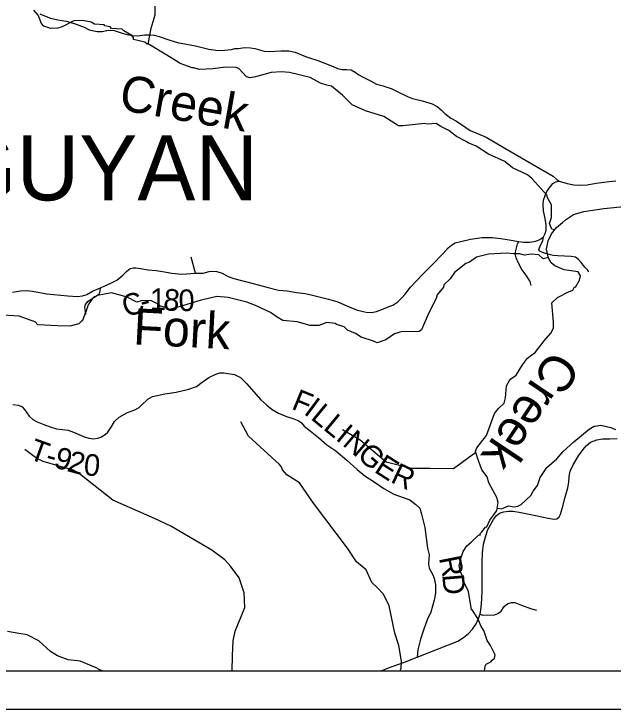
# Model space of a CAD drawing. Extents: x -1.8 to 75.7, y -2 to 25.
# Drawn here: x 45.012 to 46.582, y 15.612 to 17.434 of the extents above; entities that cross this region are included whole.
import ezdxf

# ---------------------------------------------------------------- set-up
doc = ezdxf.new("R2010")
doc.units = 0
for name, color, linetype in [('GM_X_County_Road', 7, 'Continuous'), ('GM_X_County_Road_Text', 7, 'Continuous'), ('GM_X_Minor_River', 7, 'Continuous'), ('GM_X_Minor_River_Text', 7, 'Continuous'), ('GM_X_State_Route', 7, 'Continuous'), ('GM_X_Township', 7, 'Continuous'), ('GM_X_Township_Road', 7, 'Continuous'), ('GM_X_Township_Road_Text', 7, 'Continuous'), ('GM_X_Township_ROW', 7, 'Continuous'), ('GM_X_Township_Text', 7, 'Continuous'), ('SH_Data', 7, 'Continuous')]:
    doc.layers.add(name, color=color, linetype=linetype)

msp = doc.modelspace()

# ---------------------------------------------------------------- linework, layer by layer
at = {"layer": 'GM_X_County_Road'}
for points in [[(45.08, 17.4349), (45.0918, 17.4291), (45.108, 17.423), (45.1272, 17.419), (45.1501, 17.4154), (45.1749, 17.4076), (45.196, 17.3993), (45.209, 17.3928), (45.2305, 17.3881), (45.2428, 17.3881), (45.2553, 17.391), (45.2654, 17.3917), (45.2744, 17.3908), (45.2957, 17.3841), (45.3087, 17.3805), (45.323, 17.3778), (45.3355, 17.3767), (45.3537, 17.3791), (45.3676, 17.3798), (45.3794, 17.3787), (45.3924, 17.3751), (45.4155, 17.3673), (45.4344, 17.3614), (45.4443, 17.3589)], [(45.4443, 17.3589), (45.4502, 17.3574), (45.4878, 17.3507), (45.523, 17.3424), (45.5414, 17.3391), (45.5555, 17.3382), (45.5819, 17.3415), (45.591, 17.3433), (45.5998, 17.3441), (45.6171, 17.3462), (45.6323, 17.3451), (45.6437, 17.3433), (45.6681, 17.337), (45.6827, 17.3355), (45.7114, 17.3379), (45.7324, 17.3377), (45.7492, 17.3341), (45.7759, 17.3229), (45.7865, 17.3193)], [(45.7865, 17.3193), (45.8081, 17.312), (45.8287, 17.3048), (45.8484, 17.2963), (45.8599, 17.2916), (45.8717, 17.2887), (45.8847, 17.2889), (45.8957, 17.2882), (45.9065, 17.2817), (45.9158, 17.2748), (45.9275, 17.2685), (45.9479, 17.258), (45.9619, 17.2503), (45.9797, 17.2456)], [(45.9797, 17.2456), (45.9837, 17.2445), (46.0008, 17.2389), (46.0182, 17.2304), (46.0417, 17.2185), (46.0436, 17.2178)], [(46.0436, 17.2178), (46.0568, 17.2125), (46.0814, 17.2062), (46.1076, 17.1986), (46.1213, 17.1919), (46.1316, 17.1832), (46.1416, 17.1729), (46.1573, 17.161), (46.1719, 17.1529), (46.1961, 17.1368), (46.2079, 17.129), (46.233, 17.1184), (46.2492, 17.1117), (46.2982, 17.0826), (46.369, 17.0414), (46.425, 17.0091), (46.435, 17.0001), (46.4411, 16.9957)], [(45.0082, 16.7053), (45.0296, 16.7086), (45.0449, 16.709), (45.0605, 16.7072), (45.0984, 16.7009), (45.1531, 16.6953), (45.1789, 16.6935), (45.1914, 16.6951), (45.2029, 16.699), (45.2177, 16.7072), (45.2384, 16.7167), (45.2501, 16.7216), (45.2643, 16.7281), (45.2812, 16.7367), (45.2973, 16.7494), (45.3066, 16.7588), (45.3119, 16.7632), (45.3168, 16.767), (45.324, 16.7688), (45.3317, 16.769), (45.344, 16.767), (45.3638, 16.7632), (45.3845, 16.7614), (45.4015, 16.759), (45.4261, 16.7546), (45.4522, 16.7525), (45.4875, 16.7551), (45.508, 16.7551), (45.5236, 16.7588), (45.5336, 16.76), (45.5434, 16.759), (45.5573, 16.7546), (45.5731, 16.7463), (45.5885, 16.7409), (45.6385, 16.7274), (45.678, 16.7169), (45.7055, 16.7104), (45.7278, 16.7081), (45.7522, 16.7041), (45.7755, 16.7011), (45.7941, 16.6972), (45.8364, 16.6867), (45.8604, 16.6797), (45.8862, 16.6686), (45.9097, 16.6588), (45.9276, 16.6539), (45.9353, 16.6526), (45.9488, 16.6521), (45.9625, 16.6541), (45.9804, 16.6614), (45.9911, 16.6658), (46.0048, 16.6711), (46.0183, 16.6797), (46.0286, 16.69), (46.0369, 16.7), (46.0516, 16.7179), (46.0825, 16.7514), (46.1081, 16.777), (46.1367, 16.8065), (46.1502, 16.8212), (46.1583, 16.8284), (46.1684, 16.8342), (46.1828, 16.8381), (46.2084, 16.8439), (46.2393, 16.8484), (46.2649, 16.8481), (46.2881, 16.8458), (46.31, 16.8419), (46.3349, 16.8379), (46.347, 16.8363), (46.3642, 16.8358), (46.3798, 16.8384), (46.3898, 16.843), (46.4, 16.8502), (46.4041, 16.8591), (46.4066, 16.8671), (46.4066, 16.8819), (46.4041, 16.8985), (46.3999, 16.9184), (46.3985, 16.9352), (46.4001, 16.946), (46.4039, 16.9587), (46.4097, 16.9708), (46.4178, 16.982), (46.4245, 16.9896), (46.4321, 16.9939), (46.4411, 16.9957)], [(46.4411, 16.9957), (46.4614, 16.9898), (46.4789, 16.9865), (46.4962, 16.9854), (46.5145, 16.9865), (46.5381, 16.9905), (46.5718, 16.9953), (46.589, 16.9966)]]:
    msp.add_lwpolyline(points, dxfattribs=at)
at = {"layer": 'GM_X_Minor_River'}
for points in [[(45.3634, 17.3541), (45.3715, 17.3971), (45.382, 17.4317), (45.382, 17.4571), (45.371, 17.5429), (45.3616, 17.5812), (45.3409, 17.6483), (45.323, 17.6933), (45.2876, 17.7726), (45.2847, 17.7773)], [(46.4287, 16.868), (46.4214, 16.8704), (46.4154, 16.8852), (46.421, 16.9005), (46.421, 16.9092), (46.4203, 16.9335), (46.4093, 16.9536), (46.4093, 16.9586), (46.3703, 17.0022), (46.3582, 17.0128), (46.3181, 17.0313), (46.2984, 17.0472), (46.2557, 17.0665), (46.2232, 17.0874), (46.202, 17.0968), (46.1986, 17.0991), (46.1717, 17.1127), (46.1513, 17.129), (46.1309, 17.1392), (46.1188, 17.1468), (46.0961, 17.1456), (46.0878, 17.1471), (46.0311, 17.1409), (46.0194, 17.1408), (45.9812, 17.1651), (45.9331, 17.1801), (45.898, 17.1964), (45.8734, 17.2218), (45.8446, 17.2449), (45.8352, 17.2468), (45.8318, 17.2479), (45.8151, 17.2528), (45.7883, 17.2676), (45.7342, 17.2811), (45.713, 17.2826), (45.6862, 17.2806), (45.6454, 17.2695), (45.631, 17.2664), (45.6216, 17.2698), (45.6015, 17.2911), (45.5943, 17.2941), (45.5675, 17.2951), (45.5331, 17.2901), (45.4979, 17.2885), (45.4828, 17.2934), (45.479, 17.2934), (45.4473, 17.3047), (45.4284, 17.3168), (45.3796, 17.3467), (45.3618, 17.357), (45.3607, 17.355), (45.3554, 17.3607), (45.3399, 17.3634), (45.3251, 17.3675), (45.3255, 17.3721), (45.3213, 17.3777), (45.3001, 17.3902), (45.2956, 17.3948), (45.268, 17.3959), (45.2642, 17.4004), (45.2502, 17.4034), (45.2483, 17.4057), (45.223, 17.4071), (45.2143, 17.4128), (45.192, 17.4169), (45.1689, 17.4165), (45.138, 17.4008), (45.1266, 17.397), (45.1085, 17.3962), (45.0903, 17.4022), (45.0843, 17.4094), (45.0756, 17.4315), (45.0638, 17.4443)], [(46.3449, 16.5143), (46.3582, 16.5317), (46.3692, 16.5408), (46.3783, 16.5465), (46.4013, 16.5774), (46.4187, 16.5972), (46.4258, 16.6109), (46.4258, 16.6265), (46.4212, 16.6766), (46.436, 16.6911), (46.4666, 16.7064), (46.4707, 16.7075), (46.4764, 16.7106), (46.4809, 16.7189), (46.484, 16.7178), (46.4938, 16.7368), (46.4964, 16.7482), (46.4907, 16.7585), (46.4537, 16.7633), (46.4291, 16.7743), (46.4196, 16.7823), (46.4132, 16.7944), (46.4075, 16.8176), (46.4116, 16.8392), (46.4211, 16.8583), (46.4335, 16.8743), (46.4498, 16.888), (46.457, 16.8945), (46.4785, 16.9082), (46.5053, 16.9166), (46.5575, 16.9243), (46.618, 16.9306)], [(46.4128, 16.7961), (46.3992, 16.7925), (46.3871, 16.8027), (46.3678, 16.8042), (46.3501, 16.8019), (46.3368, 16.8056), (46.3209, 16.8056), (46.3032, 16.8074), (46.2556, 16.8043), (46.2242, 16.797), (46.2057, 16.7833), (46.1958, 16.7798), (46.1664, 16.7566), (46.1554, 16.7402), (46.1388, 16.7238), (46.1373, 16.7185), (46.1207, 16.6983), (46.1184, 16.6881), (46.0981, 16.6492), (46.0796, 16.6066), (46.0743, 16.6021), (46.0629, 16.6009), (46.0293, 16.602), (46.0096, 16.5958), (45.9862, 16.5798), (45.9636, 16.5718), (45.9545, 16.5767), (45.922, 16.5869), (45.9072, 16.5963), (45.8864, 16.6058), (45.8773, 16.6141), (45.8596, 16.6194), (45.8569, 16.6205), (45.8539, 16.6232), (45.832, 16.6258), (45.8108, 16.6178), (45.7885, 16.6173), (45.7545, 16.6275), (45.717, 16.6308), (45.7019, 16.6395), (45.6845, 16.6513), (45.6448, 16.6698), (45.6225, 16.6792), (45.573, 16.6909), (45.5438, 16.6935), (45.5102, 16.6858), (45.5026, 16.6839), (45.4392, 16.6651), (45.4191, 16.6593), (45.4078, 16.6658), (45.3949, 16.6684), (45.3881, 16.6748), (45.3703, 16.6828), (45.3458, 16.6827), (45.3344, 16.6789), (45.3091, 16.6917), (45.2872, 16.6978), (45.2679, 16.703), (45.2308, 16.6965), (45.2195, 16.6907), (45.2063, 16.6717), (45.2006, 16.6538), (45.1999, 16.6519), (45.1912, 16.6287), (45.1905, 16.631), (45.1818, 16.6222), (45.1587, 16.6161), (45.1258, 16.6171), (45.0748, 16.6193), (45.0672, 16.6276), (45.057, 16.6303), (45.0256, 16.6423), (44.9701, 16.646)], [(46.1822, 16.0026), (46.1826, 16.0053), (46.189, 16.025), (46.1992, 16.0403), (46.2101, 16.0494), (46.2298, 16.0677), (46.2347, 16.0692), (46.2332, 16.0715), (46.2384, 16.0765), (46.2475, 16.0894), (46.2509, 16.0902), (46.2592, 16.1077), (46.2698, 16.1214), (46.2777, 16.1328), (46.2811, 16.1537), (46.2784, 16.1632), (46.2777, 16.167), (46.2561, 16.2053), (46.2519, 16.2205), (46.2383, 16.2391), (46.2266, 16.2706), (46.2216, 16.2885), (46.225, 16.2972), (46.2503, 16.3296), (46.2711, 16.3867), (46.2816, 16.4004), (46.2971, 16.4137), (46.3005, 16.4282), (46.3024, 16.4593), (46.3107, 16.4734), (46.3144, 16.4776), (46.3284, 16.4871), (46.3449, 16.5143)], [(46.0239, 15.7121), (46.027, 15.7197), (46.028, 15.7375), (46.0205, 15.7784), (46.0098, 15.811), (45.9957, 15.8828), (45.9807, 15.9133), (45.9639, 15.9305), (45.9503, 15.9439), (45.9351, 15.977), (45.91, 15.9983), (45.8861, 16.0336), (45.7971, 16.1523), (45.7605, 16.2051), (45.7272, 16.2262), (45.7155, 16.2391), (45.712, 16.2484), (45.7083, 16.253), (45.6267, 16.3278), (45.6066, 16.3652)], [(46.2787, 16.1387), (46.2898, 16.1366), (46.3076, 16.145), (46.3227, 16.1424), (46.3325, 16.1443), (46.3412, 16.1485), (46.3669, 16.1718), (46.3729, 16.1836), (46.3843, 16.198), (46.3914, 16.2193), (46.4088, 16.2456), (46.4345, 16.2681), (46.4511, 16.2875), (46.479, 16.3123), (46.5191, 16.3462), (46.5323, 16.3534), (46.5353, 16.3538), (46.5504, 16.3565), (46.5758, 16.3501), (46.5883, 16.3448)], [(46.2226, 16.2849), (46.1642, 16.2419), (46.103, 16.2428), (46.0535, 16.2428), (45.9878, 16.2593), (45.9193, 16.317), (45.8729, 16.3439)], [(45.5836, 15.7121), (45.5844, 15.7519), (45.5865, 15.7914), (45.5916, 15.8165), (45.6174, 15.8781), (45.6149, 15.9172), (45.6022, 15.9559), (45.5796, 15.9869), (45.5647, 16.0032), (45.5308, 16.0284), (45.423, 16.092), (45.3807, 16.1119), (45.2708, 16.1595), (45.1834, 16.2285), (45.1674, 16.2387), (45.0884, 16.261), (45.0724, 16.2689), (45.0407, 16.293)], [(46.2454, 15.7121), (46.2467, 15.7246), (46.2497, 15.7295), (46.2614, 15.7364), (46.2648, 15.7402), (46.2716, 15.7455), (46.2731, 15.7543), (46.261, 15.7786), (46.2519, 15.7922), (46.2436, 15.8177), (46.2364, 15.8287), (46.2277, 15.8496), (46.2129, 15.8723), (46.2107, 15.8727), (46.2031, 15.9206), (46.1883, 15.9506), (46.1864, 15.9623), (46.1811, 15.9733), (46.1788, 15.9889), (46.1822, 16.0026)], [(45.2431, 15.7121), (45.2351, 15.7163), (45.2258, 15.7208), (45.1854, 15.7373), (45.1542, 15.7413), (45.1258, 15.7517), (45.1076, 15.7633), (45.0771, 15.7912), (45.0469, 15.8066), (45.0251, 15.8099), (44.9947, 15.8158)]]:
    msp.add_lwpolyline(points, dxfattribs=at)
at = {"layer": 'GM_X_State_Route'}
msp.add_lwpolyline([(45.9744, 15.7121), (45.9939, 15.7205), (46.0357, 15.7355), (46.0689, 15.7481), (46.1511, 15.7801), (46.1753, 15.7904), (46.1904, 15.7994), (46.2036, 15.8099), (46.2138, 15.8214), (46.223, 15.8356), (46.2295, 15.8492), (46.2337, 15.861), (46.2365, 15.878), (46.2378, 15.9003), (46.2387, 15.9233), (46.2391, 15.9956), (46.2402, 16.0221), (46.2426, 16.0446), (46.2477, 16.064), (46.2542, 16.0832), (46.2691, 16.109), (46.2767, 16.1195), (46.2866, 16.1265), (46.2957, 16.1289), (46.3078, 16.1305), (46.3194, 16.1305), (46.3362, 16.1281), (46.3622, 16.1228), (46.4118, 16.1123), (46.4275, 16.1099), (46.4343, 16.111), (46.4409, 16.1158), (46.4444, 16.123), (46.4492, 16.1407), (46.4568, 16.1672), (46.4632, 16.1921), (46.4658, 16.2072), (46.4669, 16.2222), (46.4699, 16.2362), (46.4776, 16.2526), (46.4918, 16.2762), (46.5036, 16.2928), (46.5117, 16.3018), (46.5233, 16.3116), (46.5399, 16.318), (46.5545, 16.3202), (46.5737, 16.3208), (46.5925, 16.3217)], dxfattribs=at)
at = {"layer": 'GM_X_Township'}
msp.add_lwpolyline([(43.8002, 18.978), (43.8002, 15.7121), (47.7632, 15.7121)], dxfattribs=at)
at = {"layer": 'GM_X_Township_Road'}
for points in [[(46.5182, 16.7573), (46.5147, 16.7632), (46.5084, 16.7702), (46.4984, 16.783), (46.4919, 16.7909), (46.4835, 16.7963), (46.4724, 16.7988), (46.4372, 16.8), (46.4249, 16.8007), (46.4109, 16.8049), (46.3972, 16.8093), (46.3896, 16.8123), (46.3875, 16.8167), (46.3912, 16.8258), (46.3982, 16.8405), (46.4, 16.8502)], [(46.367, 16.7228), (46.3647, 16.7328), (46.3568, 16.7456), (46.3514, 16.7532), (46.3428, 16.7642), (46.3342, 16.7809), (46.3281, 16.7949), (46.3258, 16.8051), (46.3277, 16.8181), (46.3312, 16.8319), (46.3349, 16.8379)], [(45.2001, 16.6465), (45.1994, 16.6541), (45.1982, 16.6646), (45.1994, 16.6728), (45.2066, 16.6811), (45.2359, 16.7009), (45.238, 16.7076), (45.2384, 16.7167)], [(45.0091, 16.4101), (45.0239, 16.4089), (45.0335, 16.4041), (45.04, 16.3971), (45.0519, 16.3801), (45.0613, 16.3715), (45.073, 16.3648), (45.0907, 16.3581), (45.107, 16.3516), (45.1235, 16.3466), (45.1391, 16.3454), (45.154, 16.3432), (45.1683, 16.3382), (45.1941, 16.3265), (45.2081, 16.3219), (45.2201, 16.3202), (45.2316, 16.3219), (45.2394, 16.3247), (45.2512, 16.3317), (45.2577, 16.338), (45.267, 16.3509), (45.2756, 16.3657), (45.2881, 16.377), (45.3094, 16.3895), (45.3288, 16.3969), (45.3398, 16.4024), (45.3455, 16.4082), (45.3626, 16.4248), (45.3753, 16.4314), (45.4071, 16.4386), (45.4368, 16.4431), (45.4706, 16.451), (45.49, 16.458), (45.5053, 16.4694), (45.5226, 16.4812), (45.5408, 16.4898), (45.5518, 16.4934), (45.5611, 16.4934), (45.5896, 16.4893), (45.6057, 16.4812), (45.6222, 16.4647), (45.6402, 16.4445), (45.6593, 16.4225), (45.6744, 16.4089), (45.689, 16.3978), (45.7055, 16.388), (45.7264, 16.3794), (45.7455, 16.3727), (45.7582, 16.3677), (45.7652, 16.3626), (45.7729, 16.3534), (45.7879, 16.3416), (45.8097, 16.3243), (45.8322, 16.3044), (45.8557, 16.2889), (45.8847, 16.2647), (45.9113, 16.2398), (45.9311, 16.2232), (45.9556, 16.2082), (45.9812, 16.1907), (46.0073, 16.1756), (46.0322, 16.1665), (46.0492, 16.1603), (46.0653, 16.1483), (46.0753, 16.1387), (46.0804, 16.1231), (46.0885, 16.0884), (46.0959, 16.0336), (46.1005, 16.0163), (46.0986, 15.9924), (46.0998, 15.9818), (46.1091, 15.9658), (46.1136, 15.955), (46.117, 15.9382), (46.1165, 15.9157), (46.1132, 15.8978), (46.1043, 15.8664), (46.0952, 15.8462), (46.0851, 15.8187), (46.0772, 15.7954), (46.0703, 15.7677), (46.0689, 15.7481)], [(46.2337, 15.861), (46.2411, 15.8581), (46.2717, 15.8595), (46.28, 15.863), (46.2888, 15.8689), (46.2969, 15.8814), (46.3027, 15.8861), (46.307, 15.8887), (46.316, 15.8914), (46.3246, 15.8912), (46.3424, 15.8846), (46.3658, 15.8757), (46.3811, 15.8711)]]:
    msp.add_lwpolyline(points, dxfattribs=at)
at = {"layer": 'GM_X_Township_ROW'}
msp.add_lwpolyline([(45.4875, 16.7551), (45.4766, 16.797)], dxfattribs=at)
at = {"layer": 'SH_Data'}
for p, q in [((43.8002, 15.7121), (50.6002, 15.7121)), ((43.8002, 15.7121), (50.6002, 15.7121)), ((43.7002, 15.6121), (50.7002, 15.6121))]:
    msp.add_line(p, q, dxfattribs=at)

# ---------------------------------------------------------------- texts
at = {"layer": 'GM_X_County_Road_Text'}
for s, rotation, p in [('1', 359.5811, (45.3681, 16.6585)), ('8', 354.6607, (45.4018, 16.6583)), ('0', 1.4818, (45.444, 16.6548)), ('C', 18.9515, (45.3064, 16.6381)), ('-', 14.9583, (45.3495, 16.6529))]:
    msp.add_text(s, height=0.0568, rotation=rotation, dxfattribs=at).set_placement(p)
at = {"layer": 'GM_X_Minor_River_Text'}
for s, rotation, p in [('Creek', 350.0126, (45.2841, 17.1839)), ('Fork', 357.013, (45.3233, 16.5684)), ('Creek', 236.1304, (46.4217, 16.5578))]:
    msp.add_text(s, height=0.09469, rotation=rotation, dxfattribs=at).set_placement(p)
at = {"layer": 'GM_X_Township_Road_Text'}
for s, rotation, p in [('F', 337.6802, (45.7368, 16.3999)), ('I', 323.4986, (45.769, 16.3872)), ('L', 320.6334, (45.7872, 16.3738)), ('L', 320.4721, (45.82, 16.3468)), ('I', 320.4393, (45.8528, 16.3198)), ('N', 319.5629, (45.8706, 16.3051)), ('T', 340.1352, (45.0479, 16.2689)), ('9', 343.8492, (45.1141, 16.2466)), ('G', 319.276, (45.9086, 16.2727)), ('-', 343.5921, (45.0915, 16.2533)), ('2', 344.5951, (45.1485, 16.2366)), ('0', 354.9875, (45.1933, 16.2254)), ('E', 327.3764, (45.9535, 16.2349)), ('R', 334.7222, (45.9963, 16.2081)), ('R', 281.2384, (46.1256, 16.0084)), ('D', 274.719, (46.1344, 15.9643))]:
    msp.add_text(s, height=0.0568, rotation=rotation, dxfattribs=at).set_placement(p)
at = {"layer": 'GM_X_Township_Text'}
msp.add_text('GUYAN', height=0.17045, rotation=0, dxfattribs=at).set_placement((44.8415, 16.9456))

doc.saveas('drawing.dxf')
